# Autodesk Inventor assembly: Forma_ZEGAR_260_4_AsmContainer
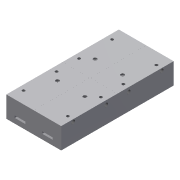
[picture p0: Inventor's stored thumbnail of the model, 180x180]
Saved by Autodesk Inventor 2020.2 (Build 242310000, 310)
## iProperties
Created: 2015-01
Part Number: Forma_ZEGAR_260_4_AsmContainer
Document SubType Name: Assembly
Designer: F.Stasiak
Catalog Web Link: www.expertbooks.pl
Manager: www.cadconsulting.pl
Company: Fabian Stasiak CAD Consulting
Author: F.Stasiak
Subject: Zbiór ćwiczeń. Autodesk Inventor 2020. Kurs Professional
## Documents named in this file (9)
- C:\2020_Kurs_Professional\R6 Formy\Komponenty\Forma_ZEGAR_260_4_AsmContainer.iam
- C:\2020_Kurs_Professional\R6 Formy\Komponenty\Forma_ZEGAR_260_5_ZEGAR_260_CR_1.ipt
- C:\2020_Kurs_Professional\R6 Formy\Komponenty\Forma_ZEGAR_260_5_ZEGAR_260_CV_1.ipt
- C:\2020_Kurs_Professional\R6 Formy\Komponenty\Forma_ZEGAR_260_5_ZEGAR_260_CR_2.ipt
- C:\2020_Kurs_Professional\R6 Formy\Komponenty\Forma_ZEGAR_260_5_ZEGAR_260_CV_2.ipt
- C:\2020_Kurs_Professional\R6 Formy\Komponenty\Forma_ZEGAR_260_5_ZEGAR_260_CR_3.ipt
- C:\2020_Kurs_Professional\R6 Formy\Komponenty\Forma_ZEGAR_260_5_ZEGAR_260_CV_3.ipt
- C:\2020_Kurs_Professional\R6 Formy\Komponenty\Forma_ZEGAR_260_5_ZEGAR_260_CR_4.ipt
- C:\2020_Kurs_Professional\R6 Formy\Komponenty\Forma_ZEGAR_260_5_ZEGAR_260_CV_4.ipt
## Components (8 placed, 8 different names)
1. Forma_ZEGAR_260_4_ZEGAR_260_CR_1:1
2. Forma_ZEGAR_260_4_ZEGAR_260_CV_1:1
3. Forma_ZEGAR_260_4_ZEGAR_260_CR_2:1
4. Forma_ZEGAR_260_4_ZEGAR_260_CV_2:1
5. Forma_ZEGAR_260_4_ZEGAR_260_CR_3:1
6. Forma_ZEGAR_260_4_ZEGAR_260_CV_3:1
7. Forma_ZEGAR_260_4_ZEGAR_260_CR_4:1
8. Forma_ZEGAR_260_4_ZEGAR_260_CV_4:1
